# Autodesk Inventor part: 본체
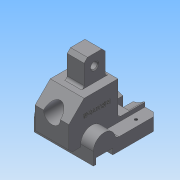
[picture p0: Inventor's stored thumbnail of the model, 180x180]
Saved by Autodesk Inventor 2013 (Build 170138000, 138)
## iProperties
Created: 2016-11
Part Number: 본체
Material: 일반
Document SubType Name: Modeling
Designer: Administrator
Density: 1 g/cm^3
Author: Administrator
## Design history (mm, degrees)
sketch "스케치1"
  geometry: L1 (35, 38)-(-35, 38); L2 (-35, 38)-(-35, -38); L3 (-35, -38)-(35, -38); L4 (35, -38)-(35, 38); L5 (35, 38)-(-35, -38); L6 (-35, 38)-(35, -38); 1 further point
  constraints: 12 end point, 2 midpoint, 2 parallel, 1 horizontal, 1 perpendicular
  dimensions: "d0" = 70 distance of L3.end L2.end; "d1" = 76 distance of L2.end L1.end
extrude "돌출1" new body sketch "스케치1" distance "d2" = 15; taper "d3" = 0 deg
sketch "스케치2"
  geometry: L1 (0, 76)-(0, 0) reference; L2 (0, 0)-(15, 0) reference; L3 (0, 76)-(15, 76) reference; L4 (0, 73)-(7, 73); L5 (7, 73)-(7, 53); L6 (7, 53)-(0, 53); L7 (0, 53)-(0, 73); 1 further point
  constraints: 8 end point, 2 parallel, 1 collinear, 1 horizontal, 1 perpendicular
  dimensions: "d4" = 76 distance between parallel lines of L2 L3 (derived); "d5" = 3 distance between parallel lines of L4 L3; "d6" = 20 distance between parallel lines of L6 L4; "d7" = 7 distance between parallel lines of L5 L1
extrude "돌출2" cut sketch "스케치2" stored distance "d8" = 15; taper "d9" = 0 deg
sketch "스케치3"
  geometry: L1 (-15, 76)-(-15, 73) reference; L2 (0, 76)-(0, 50); A1 r 13 centre (0, 63) between (0, 50) and (0, 76); 1 further point
  constraints: 2 end point, 2 point on circle, 1 centre point, 1 parallel, 1 point on line
  dimensions: "d12" = 26 diameter of A1
extrude "돌출3" join sketch "스케치3" distance "d13" = 70; taper "d14" = 0 deg
sketch "스케치5"
  geometry: L1 (-38, 12)-(52, 12); L2 (52, 12)-(52, 42); L3 (52, 42)-(34, 60); L4 (34, 60)-(-6, 60); L5 (-6, 60)-(-6, 20); L6 (-6, 20)-(-38, 20); L7 (-38, 20)-(-38, 12); L8 (-38, 0)-(-38, 15) reference; L9 (15, 0)-(-38, 0) reference; 1 further point
  constraints: 14 end point, 4 parallel, 1 collinear, 1 horizontal, 1 perpendicular
  dimensions: "d15" = 20 distance between parallel lines of L6 L9; "d16" = 60 distance between parallel lines of L4 L9; "d17" = 48 distance between parallel lines of L4 L1; "d18" = 90 distance between parallel lines of L2 L7; "d19" = 58 distance between parallel lines of L2 L5; "d20" = 45 deg angle of L3 L4; "d21" = 30 distance of L2.end L1.end; "d22" = 18 horizontal distance of L2.end L3.end (derived)
extrude "돌출4" join sketch "스케치5" stored distance "d23" = 40; taper "d24" = 0 deg
sketch "스케치6"
  geometry: L1 (-1, 60)-(24, 60); L2 (24, 60)-(24, 90); L3 (24, 90)-(-1, 90); L4 (-1, 90)-(-1, 60); L5 (-6, 60)-(34, 60) reference; L6 (-6, 20)-(-6, 60) reference; L7 (15, 0)-(-38, 0) reference; 1 further point
  constraints: 8 end point, 2 parallel, 1 collinear, 1 horizontal, 1 perpendicular
  dimensions: "d25" = 5 distance between parallel lines of L4 L6; "d26" = 25 distance between parallel lines of L2 L4; "d27" = 90 distance between parallel lines of L3 L7
extrude "돌출5" join sketch "스케치6" stored distance "d28" = 20; taper "d29" = 0 deg
sketch "스케치7"
  geometry: L1 (55.668, 42)-(-49.043, 42); L2 (15, 0)-(-38, 0) reference; L3 (-6, 20)-(-6, 60) reference; L4 (-6, 42)-(1, 42); L5 (1, 42)-(1, 56.5); L6 (1, 56.5)-(-6, 56.5); L7 (-6, 56.5)-(-6, 42); L8 (1, 42)-(52, 42); L9 (52, 42)-(52, 52); L10 (52, 52)-(1, 52); L11 (1, 52)-(1, 42); L12 (52, 42)-(52, 12) reference; L13 (52, 12)-(38, 12) reference; 1 further point
  constraints: 18 end point, 4 parallel, 3 horizontal, 2 perpendicular, 2 point on line, 1 collinear
  dimensions: "d32" = 29 diameter of L6 L1; "d34" = 20 diameter of L10 L1; "d35" = 7 distance between parallel lines of L5 L3; "d76" = 30 distance between parallel lines of L1 L13
revolve "회전1" sketch "스케치7" stored, may be unused: angle "d36" = 90 deg
sketch "스케치8"
  geometry: L1 (-27.5, -38)-(27.5, -38); L2 (27.5, -38)-(27.5, -20); L3 (27.5, -20)-(-27.5, -20); L4 (-27.5, -20)-(-27.5, -38); L5 (-20, -38)-(20, -38) reference; 6 further points
  constraints: 8 end point, 4 coincident, 3 midpoint, 2 parallel, 1 horizontal, 1 perpendicular
  dimensions: "d37" = 18 distance between parallel lines of L3 L1; "d39" = 55 distance between parallel lines of L2 L4
hole "구멍1" sketch "스케치8" at (-27.5, -20), (27.5, -20) diameter "d40" = 3.242; stored, may be unused: countersink angle "d44" = 90 deg, drill point angle "d46" = 118 deg; dims "d41" = 16, "d42" = 4, "d43" = 2, "d45" = 8
sketch "스케치9"
  geometry: L1 (90, 24)-(60, 24) reference; L2 (0, 15)-(0, -38) reference; 2 further points
  dimensions: "d47" = 12.5 distance from line of point (77, 11.5) L1; "d48" = 77 distance from line of point (77, 11.5) L2
hole "구멍2" sketch "스케치9" at (77, 11.5) diameter "d49" = 8; stored, may be unused: countersink angle "d53" = 90 deg, drill point angle "d55" = 118 deg; dims "d50" = 16, "d51" = 4, "d52" = 2, "d54" = 8
sketch "스케치11"
  geometry: L1 (0, 0)-(70, 0) reference; L2 (29, 0)-(41, 0); L3 (41, 0)-(41, 20); L4 (41, 20)-(29, 20); L5 (29, 20)-(29, 0); L6 (15, 20)-(55, 20) reference; 4 further points
  constraints: 8 end point, 3 midpoint, 2 coincident, 2 parallel, 1 collinear, 1 horizontal, 1 perpendicular
  dimensions: "d61" = 12 distance between parallel lines of L3 L5
extrude "돌출7" cut sketch "스케치11" distance "d64" = 18; taper "d65" = 0 deg
chamfer "모따기1" distance "d66" = 5; stored, may be unused: second distance "d67" = 2, angle "d68" = 45 deg
chamfer "모따기2" distance "d69" = 4; stored, may be unused: second distance "d70" = 2, angle "d71" = 45 deg
fillet "모깎기1" dims "d72" = 3
chamfer "모따기3" distance "d73" = 1; stored, may be unused: second distance "d74" = 2, angle "d75" = 45 deg
fillet "모깎기2" dims "d77" = 3
sketch "스케치12"
  geometry: C1 r 29 at (-20, 27); C2 r 11 at (-20, 27) reference; 1 further point
  constraints: 1 centre point, 1 concentric
  dimensions: "d79" = 58 diameter of C1
extrude "돌출8" cut sketch "스케치12" distance "d80" = 18; taper "d81" = 0 deg
sketch "스케치13"
  geometry: L1 (23, -6)-(60, -6) reference; L2 (60, -6)-(60, 34) reference; 2 further points
  constraints: 1 other
  dimensions: "d82" = 25 distance from line of L1 point (42, 19); "d83" = 18 distance from line of point (42, 19) L2
feature "엠보싱1" sketch "스케치13" dims "d0" = 70, "d1" = 76, "d84" = 0.5, "d85" = 0
chamfer "모따기4" distance "d86" = 4; stored, may be unused: second distance "d87" = 2, angle "d88" = 45 deg
fillet "모깎기3" dims "d89" = 5
node "솔리드1"
